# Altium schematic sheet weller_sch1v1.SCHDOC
size B
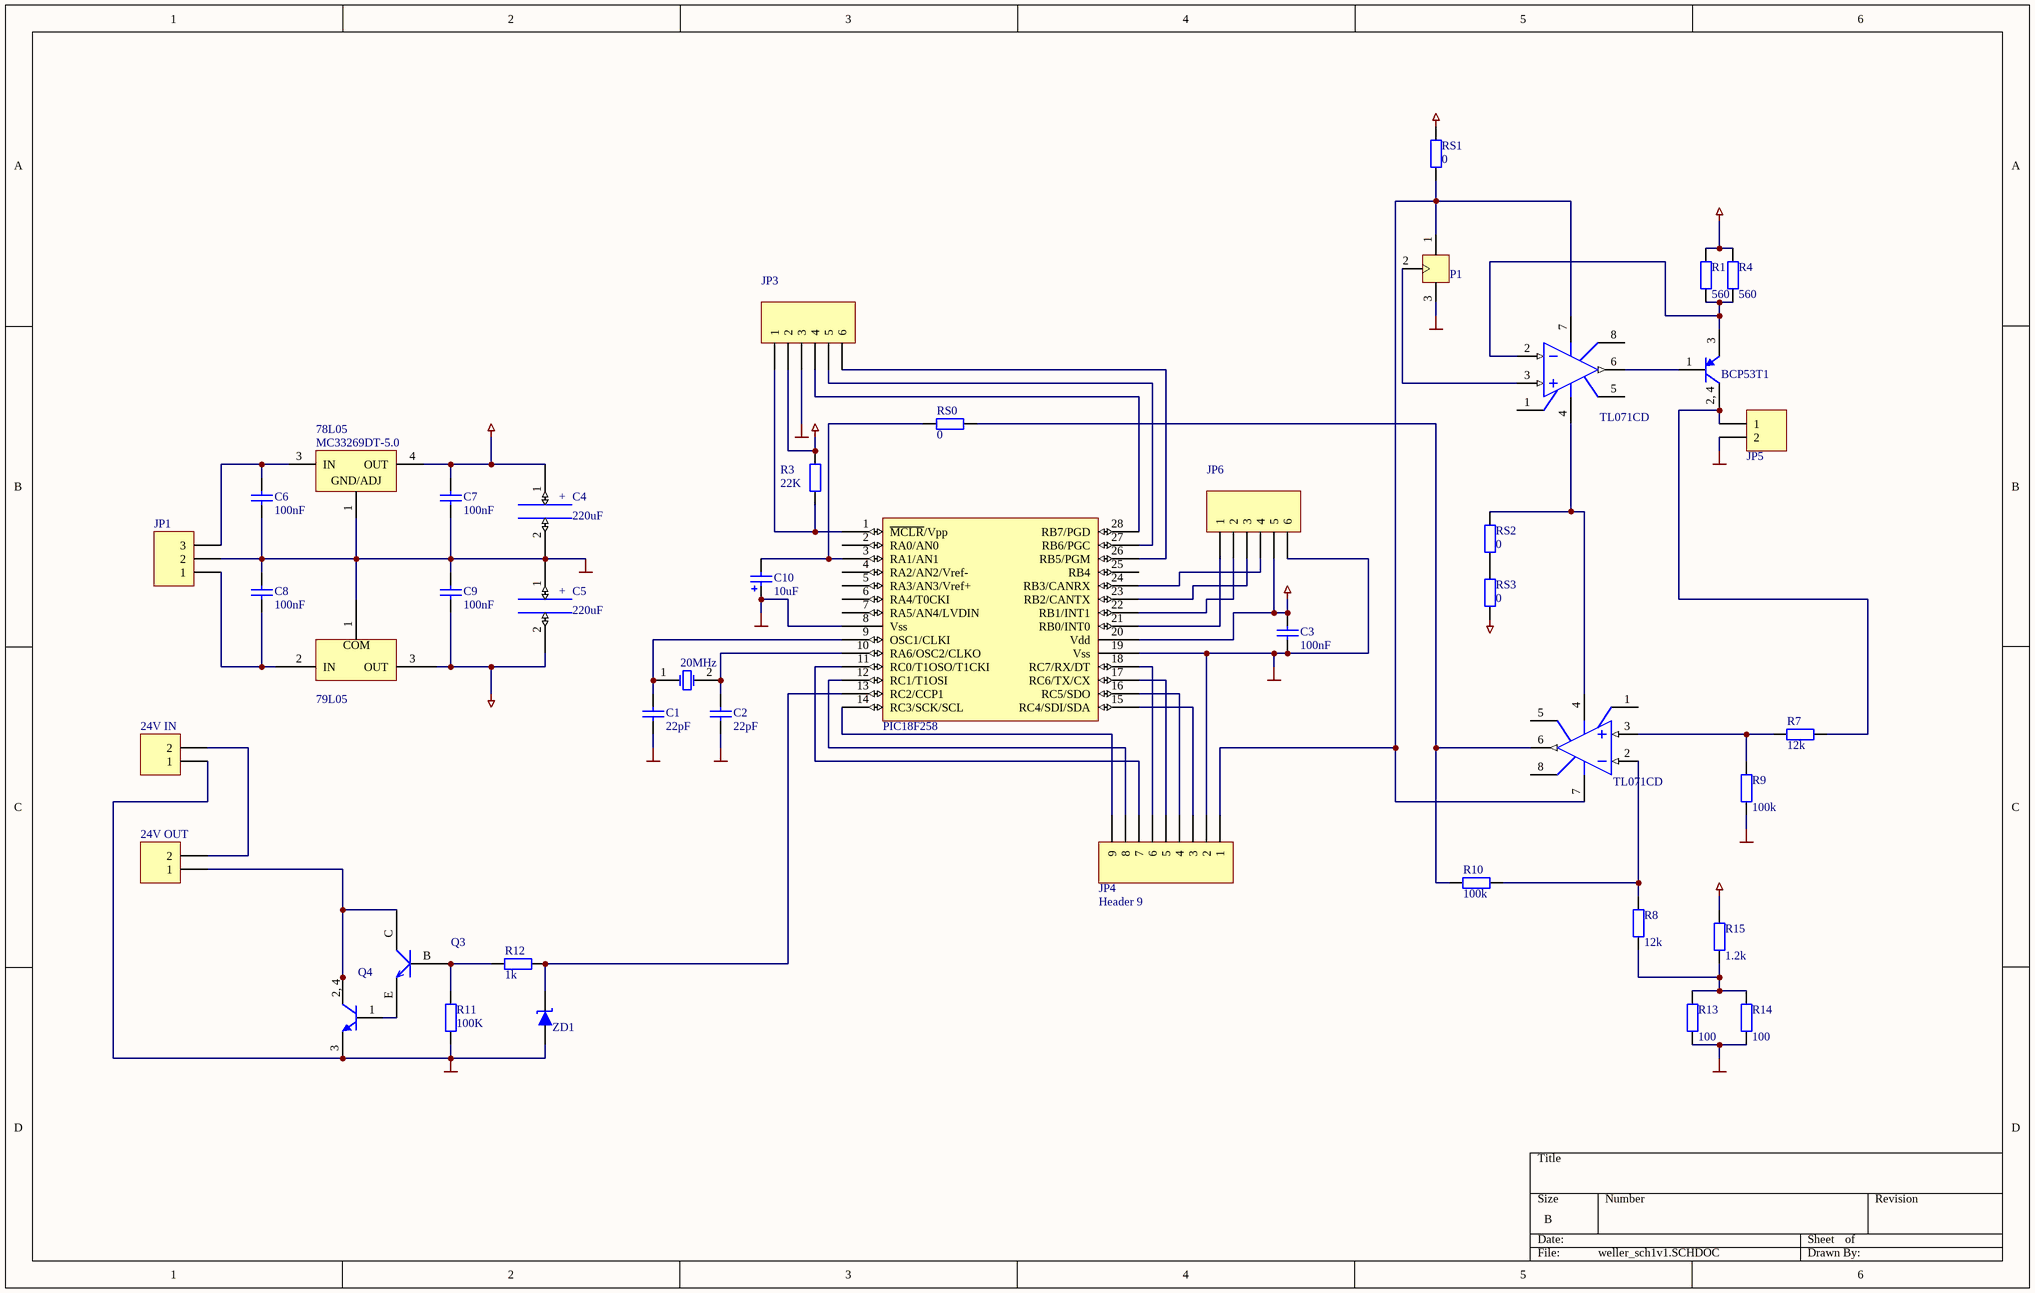
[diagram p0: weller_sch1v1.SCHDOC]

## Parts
20MHz  ECS-110-S-5P  [BCY-F2/Z13]  (value not drawn)
24V_IN  Header 2  [HDR1X2]  (value not drawn)
24V_OUT  Header 2  [HDR1X2]  (value not drawn)
78L05  MC33269DT-5.0  [SIP-G3/Z11.05]
7905  79L05  [SOT89/P1.5]
amp_1  TL071CD  [SO-G8]
amp_2  TL071CD  [SO-G8]
C1  value 22pF  [C3216-1206]  (hidden comment: Cap Semi)
C2  value 22pF  [C3216-1206]  (hidden comment: Cap Semi)
C3  value 100nF  [C3216-1206]  (hidden comment: Cap Semi)
C4  value 220uF  [DSO-C3/X3.4]
C5  value 220uF  [DSO-C3/X3.4]
C6  value 100nF  [C3216-1206]  (hidden comment: Cap Semi)
C7  value 100nF  [C3216-1206]  (hidden comment: Cap Semi)
C8  value 100nF  [C3216-1206]  (hidden comment: Cap Semi)
C9  value 100nF  [C3216-1206]  (hidden comment: Cap Semi)
C10  value 10uF  [DSO-F2/D6.1]  (hidden comment: Cap Pol3)
JP1  Header 3  [HDR1X3]  (value not drawn)
JP3  Header 6  [HDR1X6]  (value not drawn)
JP4  Header 9  [HDR1X9]
JP5  Header 2  [HDR1X2]  (value not drawn)
JP6  Header 6  [HDR1X6]  (value not drawn)
P1  SMD POTI  [SMD poti]  (value not drawn)
PIC18F258  (no value)  [SOIC28]
Q1  BCP53T1  [DSO-G3/C6.6]
Q3  BC817  [SOT23]  (value not drawn)
Q4  BCP56T1  [DSO-G3/C6.6]  (value not drawn)
R1  value 560  [C3216-1206]  (hidden comment: Res2)
R3  value 22K  [C3216-1206]  (hidden comment: Res2)
R4  value 560  [C3216-1206]  (hidden comment: Res2)
R7  value 12k  [C3216-1206]  (hidden comment: Res2)
R8  value 12k  [C3216-1206]  (hidden comment: Res2)
R9  value 100k  [C3216-1206]  (hidden comment: Res2)
R10  value 100k  [C3216-1206]  (hidden comment: Res2)
R11  value 100K  [C3216-1206]  (hidden comment: Res2)
R12  value 1k  [C3216-1206]  (hidden comment: Res2)
R13  value 100  [C3216-1206]  (hidden comment: Res2)
R14  value 100  [C3216-1206]  (hidden comment: Res2)
R15  value 1.2k  [C3216-1206]  (hidden comment: Res2)
RS0  value 0  [C3216-1206]  (hidden comment: Res2)
RS1  value 0  [C3216-1206]  (hidden comment: Res2)
RS2  value 0  [C3216-1206]  (hidden comment: Res2)
RS3  value 0  [C3216-1206]  (hidden comment: Res2)
ZD1  ZENER  [Dioda200]  (value not drawn)

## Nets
GND: 24V_IN.1 78L05.1(GND/ADJ) 7905.1 C1.1 C2.1 C3.1 C4.2(-) C5.1(+) C6.1 C7.1 C8.2 C9.2 C10.1 JP1.2 JP3.3 JP4.2 JP5.2 JP6.6 P1.3 PIC18F258.8(Vss) PIC18F258.19(Vss) Q4.3(E) R9.1 R11.1 R13.1 R14.1 ZD1.1
Vcc: 7905.3(OUT) C5.2(-) C9.1 RS3.2
Vdd: 78L05.4(OUT) C3.2 C4.1(+) C7.2 JP3.2 JP6.5 PIC18F258.20(Vdd) R1.2 R3.2 R4.2 R15.2 RS1.1
Net20MHz_1: 20MHz.1(OSC1) C1.2 PIC18F258.9(OSC1/CLKI)
Net20MHz_2: 20MHz.2(OSC2) C2.2 PIC18F258.10(RA6/OSC2/CLKO)
Net24V_IN_2: 24V_IN.2 24V_OUT.2
Net24V_OUT_1: 24V_OUT.1 Q3.C Q4.2(C) Q4.4(C)
Net78L05_3: 78L05.3(IN) C6.2 JP1.3
Net7905_2: 7905.2(IN) C8.1 JP1.1
Netamp_1_2: amp_1.2(IN-) Q1.3(E) R1.1 R4.1
Netamp_1_3: amp_1.3(IN+) P1.2
Netamp_1_4: amp_1.4(V-) amp_2.4(V-) RS2.1
Netamp_1_6: amp_1.6(OUT) Q1.1(B)
Netamp_1_7: amp_1.7(V+) amp_2.7(V+) JP4.1 P1.1 RS1.2
Netamp_2_2: amp_2.2(IN-) R8.2 R10.1
Netamp_2_3: amp_2.3(IN+) R7.2 R9.2
Netamp_2_6: amp_2.6(OUT) R10.2 RS0.1
NetC10_2: C10.2 PIC18F258.3(RA1/AN1) RS0.2
NetJP3_1: JP3.1 PIC18F258.1(~{MCLR}/Vpp) R3.1
NetJP3_4: JP3.4 PIC18F258.28(RB7/PGD)
NetJP3_5: JP3.5 PIC18F258.27(RB6/PGC)
NetJP3_6: JP3.6 PIC18F258.26(RB5/PGM)
NetJP4_3: JP4.3 PIC18F258.15(RC4/SDI/SDA)
NetJP4_4: JP4.4 PIC18F258.16(RC5/SDO)
NetJP4_5: JP4.5 PIC18F258.17(RC6/TX/CX)
NetJP4_6: JP4.6 PIC18F258.18(RC7/RX/DT)
NetJP4_7: JP4.7 PIC18F258.11(RC0/T1OSO/T1CKI)
NetJP4_8: JP4.8 PIC18F258.12(RC1/T1OSI)
NetJP4_9: JP4.9 PIC18F258.14(RC3/SCK/SCL)
NetJP5_1: JP5.1 Q1.2(C) Q1.4(C) R7.1
NetJP6_1: JP6.1 PIC18F258.21(RB0/INT0)
NetJP6_2: JP6.2 PIC18F258.22(RB1/INT1)
NetJP6_3: JP6.3 PIC18F258.23(RB2/CANTX)
NetJP6_4: JP6.4 PIC18F258.24(RB3/CANRX)
NetPIC18F258_13: PIC18F258.13(RC2/CCP1) R12.1 ZD1.2
NetQ3_B: Q3.B R11.2 R12.2
NetQ3_E: Q3.E Q4.1(B)
NetR8_1: R8.1 R13.2 R14.2 R15.1
NetRS2_2: RS2.2 RS3.1

Not connected (* = marked no-connect by the designer): amp_1 1(OS_NULL) 5(OS_NULL) 8(NC); amp_2 1(OS_NULL) 5(OS_NULL) 8(NC); PIC18F258 2(RA0/AN0) 4(RA2/AN2/Vref-) 5(RA3/AN3/Vref+) 6(RA4/T0CKI) 7(RA5/AN4/LVDIN) 25(RB4)

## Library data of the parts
20MHz = ECS-110-S-5P: Crystal Oscillator; Manufacturer: ECS
24V_IN 24V_OUT JP5 = Header 2: Header, 2-Pin; Manufacturer: Generic Components; Class: Connector
78L05 = MC33269DT-5.0: Low Dropout Positive Fixed Voltage Regulator; Manufacturer: ON Semiconductor; Class: Power Management; Note: Pin 2 is electrically connected to Pin 4 (TAB); Pin 2 is trimmed and not drawn
amp_1 amp_2 = TL071CD: Low-Noise J-FET Single Operational Amplifier; Manufacturer: ST-Microelectronics
C1-C3 C6-C9 = Cap Semi: Capacitor (Semiconductor SIM Model); Manufacturer: Generic Components; Class: Passive
C4 C5 = PUFFER_220U
C10 = Cap Pol3: Polarized Capacitor (Surface Mount); Manufacturer: Generic Components; Class: Passive
JP1 = Header 3: Header, 3-Pin; Manufacturer: Generic Components; Class: Connector
JP3 JP6 = Header 6: Header, 6-Pin; Manufacturer: Generic Components; Class: Connector
JP4 = Header 9: Header, 9-Pin; Manufacturer: Generic Components; Class: Connector
PIC18F258 = PIC18F258
Q1 = BCP53T1: PNP Silicon Epitaxial Transistor; Manufacturer: Motorola; Class: Discrete; SubClass: BJT - Medium Power
Q4 = BCP56T1: NPN Silicon Epitaxial Transistor; Manufacturer: Motorola; Class: Discrete; SubClass: BJT - Medium Power
R1 R3 R4 R7-R15 RS0-RS3 = Res2: Resistor; Manufacturer: Generic Components; Class: Passive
